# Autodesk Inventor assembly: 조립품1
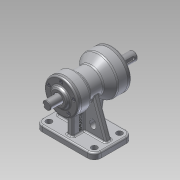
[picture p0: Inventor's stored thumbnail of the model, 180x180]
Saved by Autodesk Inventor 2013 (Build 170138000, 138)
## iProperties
Created: 2015-08
Part Number: 조립품1
Document SubType Name: Assembly
Designer: ST
Author: ST
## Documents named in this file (10)
- C:\Users\ST\Desktop\조립품1.iam
- C:\Users\ST\Desktop\M4x0.5.ipt
- C:\Users\ST\Desktop\뒤커버.ipt
- C:\Users\ST\Desktop\베어링 6203.ipt
- C:\Users\ST\Desktop\베어링 6205.ipt
- C:\Users\ST\Desktop\본체.ipt
- C:\Users\ST\Desktop\앞커버.ipt
- C:\Users\ST\Desktop\오일실 .ipt
- 오일실 .ipt
- C:\Users\ST\Desktop\축.ipt
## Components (10 placed, 1 different names)
1. M4x0.5:1
2. M4x0.5:2
3. M4x0.5:3
4. M4x0.5:4
5. M4x0.5:5
6. M4x0.5:6
7. M4x0.5:7
8. M4x0.5:8
9. M4x0.5:9
10. M4x0.5:10
